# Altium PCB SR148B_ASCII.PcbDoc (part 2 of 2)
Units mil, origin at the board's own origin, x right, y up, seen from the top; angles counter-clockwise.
Board outline 3900 x 2475 mil, 6 copper layers (Top Layer, Signal Layer 1, Signal Layer 2, Signal Layer 3, Signal Layer 4, Bottom Layer), stack 60.536 mil thick; 89 components, 26 nets, 178 pads, 295 vias.
Unrouted connection lines stored in the file: 1.
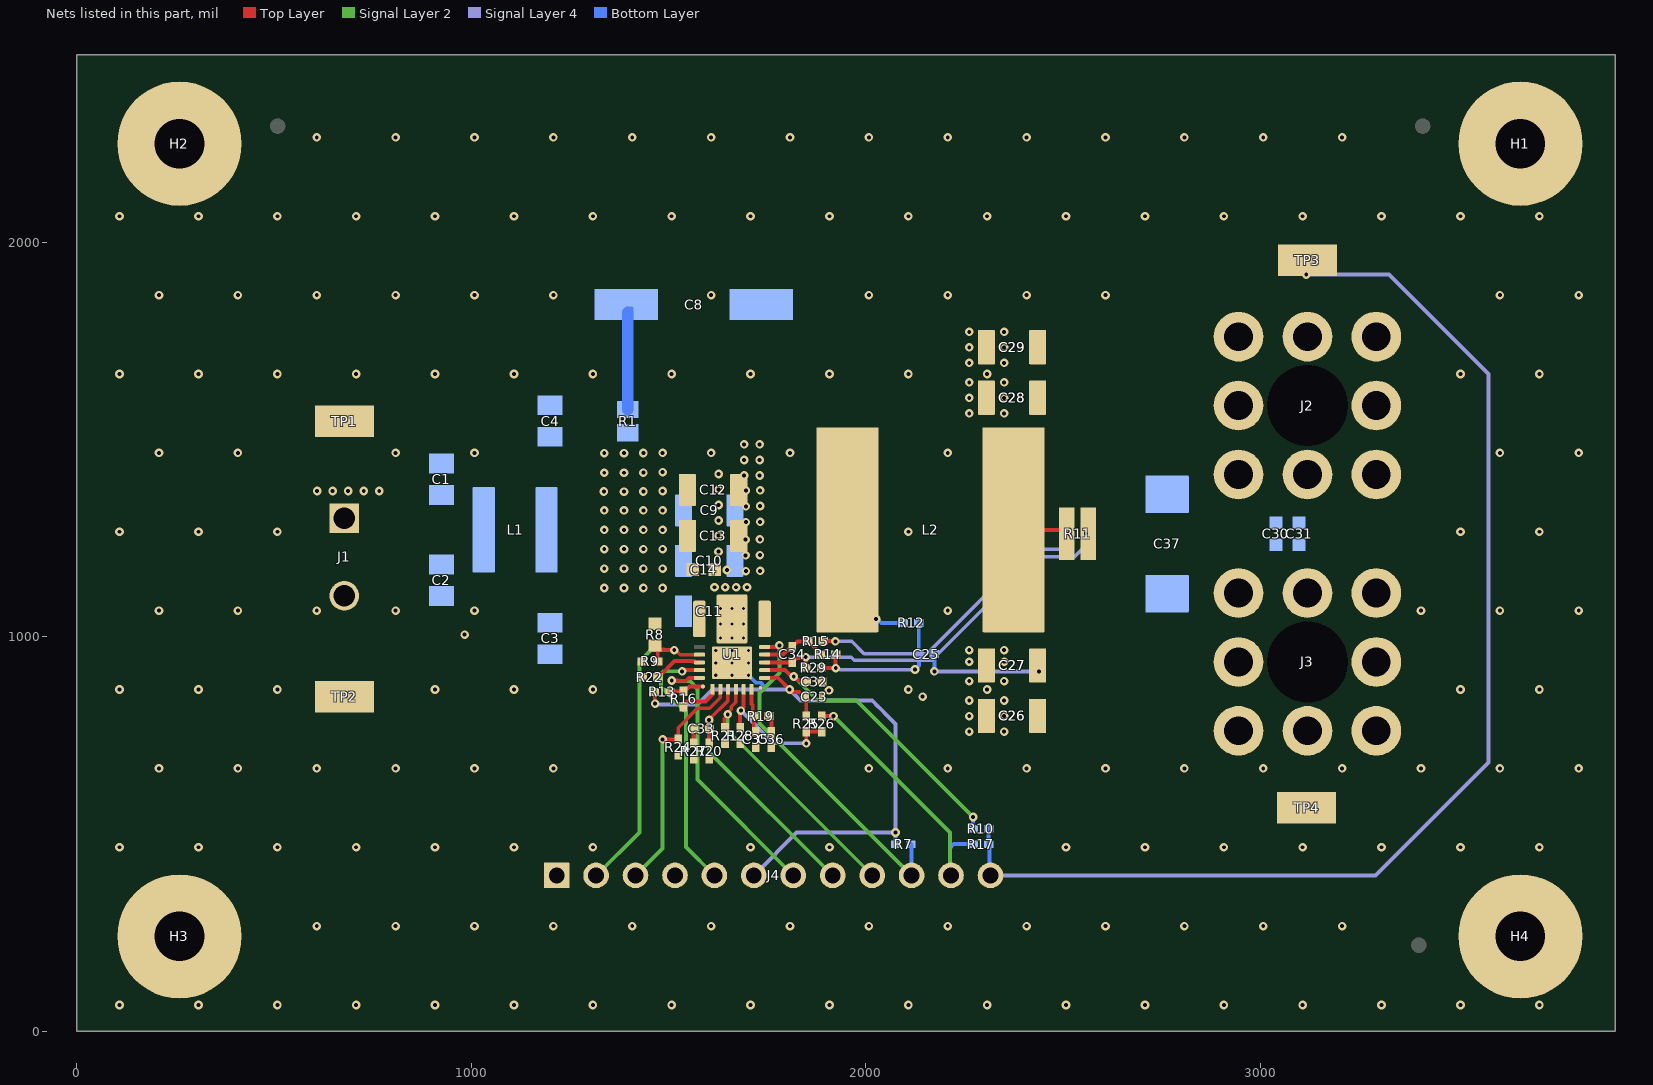
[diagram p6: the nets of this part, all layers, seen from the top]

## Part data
C1 C2 C3 C4: library part CMP-0008374-2, "CAP, CERM, 0.47 uF, 100 V, +/- 10%, X7R, 0805"
C8: library part CMP-0011203-2, "CAP, AL, 33 uF, 100 V, +/- 20%, 0.7 ohm, AEC-Q200 Grade 2, SMD"
C9 C10 C11 C12 C13: library part CMP-0087970-1, "10µF ±10% 100V Ceramic Capacitor X7S 1210 (3225 Metric)"
C14: library part CMP-0080063-1, "CAP, CERM, 0.01 µF, 100 V,+/- 10%, X8R, AEC-Q200 Grade 0, 0603"
C23: library part CMP-0086250-1, "CAP, CERM, 2.2 µF, 10 V,+/- 10%, X7S, AEC-Q200 Grade 1, 0402"
C25 C32: library part CMP-0080610-1, "CAP, CERM, 0.1 µF, 25 V,+/- 10%, X7R, AEC-Q200 Grade 1, 0402"
C26 C27 C28 C29: library part CMP-0096011-1, "Ceramic Capacitor for Automotive 47uF ±10% 10VDC X7S 1210 Embossed T/R"
C26 C27 C28 C29: library part CMP-0036912-1, "Cap Ceramic 22uF 25V X7R 20% Pad SMD 1210 +125°C Automotive T/R"
C30 C31: library part CMP-0006861-4, "CAP, CERM, 0.1 uF, 50 V, +/- 10%, X7R, 0603"
C33: library part CMP-0078224-1, "CAP, CERM, 0.01 µF, 50 V,+/- 10%, X8R, AEC-Q200 Grade 0, 0402"
C34: library part CMP-0006308-2, "CAP, CERM, 100 pF, 50 V, +/- 5%, C0G/NP0, AEC-Q200 Grade 1, 0402"
C35: library part CMP-0860832-1, "CAP, CERM, 47 pF, 50 V,+/- 5%, C0G/NP0, AEC-Q200 Grade 1, 0402"
C36: library part CMP-0006686-2, "CAP, CERM, 2700 pF, 50 V, +/- 10%, X7R, 0402"
C37: library part CMP-0124193-1, "100 µF 16 V Aluminum - Polymer Capacitors 2917 (7343 Metric) 12mOhm 2000 Hrs @ 105°C"
"CAUTION HOT SURFACE": library part CMP-0074837-2, "IEC 61010-1 Hot Surface Warning"
FID1 FID2 FID3 FID4 FID5 FID6: library part CMP-0077181-1, "Fiducial mark.  There is nothing to buy or mount."
H1 H2 H3 H4: library part CMP-0003617-1, "Machine Screw, Round, #4-40 x 1/4, Nylon, Philips panhead"
H5 H6 H7 H8: library part CMP-0003610-1, "Standoff, Hex, 0.5\"L #4-40 Nylon"
J1: library part CMP-0054978-1, "Therminal Block, 5 mm, 2-pole, Tin, TH"
J2 J3: library part CMP-0087729-1, "WP-THRSH 8 Pin PCB Screw Terminal, 85A, Solder, M5, Vertical"
J4: library part CMP-0075424-1, "Header, 100mil, 12x1, Gold, TH"
L1: library part CMP-0093175-1, "Shielded Power Inductors 3.3uH 20% tol, 6.5mOhm 16.6A"
L2: library part CMP-0123970-1, "Power Choke Coil 4.7uH 20% 100kHz 4.7mOhm 27A AECQ200 13.3x12.8x8.0mm SMT"
Logo1: library part CMP-0074844-1
Logo2: library part CMP-0074838-1, "Texas Instrument Corporate Signature"
Logo3: library part CMP-0074847-1, "FCC_disclaimer"
Logo4: library part CMP-0074769-1
R1: library part CMP-0020616-3, "RES, 0, 5%, 0.125 W, AEC-Q200 Grade 0, 0805"
R7 R29: library part CMP-0080661-1, "RES, 100 k, 1%, 0.0625 W, AEC-Q200 Grade 0, 0402"
R8: library part CMP-0022901-4, "RES, 200 k, 1%, 0.1 W, 0603"
R9 R12: library part CMP-0078779-1, "RES, 10.0 k, 1%, 0.2 W, AEC-Q200 Grade 0, 0402"
R10: library part CMP-0026129-2, "RES, 1.00, 1%, 0.063 W, AEC-Q200 Grade 0, 0402"
R11: library part CMP-0124890-1, "1 mOhms ±5% 1.5W Chip Resistor Wide 1206 (3216 Metric), 0612 Automotive AEC-Q200, Current Sense Metal Foil"
R13 R16 R26: library part CMP-0026449-2, "RES, 54.9 k, 1%, 0.063 W, AEC-Q200 Grade 0, 0402"
R14 R25 R27: library part CMP-0027007-2, "RES, 0, 5%, 0.063 W, AEC-Q200 Grade 0, 0402"
R15 R17: library part CMP-0026703-1, "RES, 49.9, 1%, 0.1 W, AEC-Q200 Grade 0, 0402"
R19: library part CMP-0025975-3, "RES, 11.0 k, 1%, 0.063 W, AEC-Q200 Grade 0, 0402"
R20: library part CMP-0026591-2, "RES, 8.66 k, 1%, 0.063 W, AEC-Q200 Grade 0, 0402"
R21 R24: library part CMP-0026605-2, "RES, 90.9 k, 1%, 0.063 W, AEC-Q200 Grade 0, 0402"
R22: library part CMP-0026187-2, "RES, 23.7 k, 1%, 0.063 W, AEC-Q200 Grade 0, 0402"
R28: library part CMP-0026783-1, "RES, 4.99 k, 0.1%, 0.063 W, 0402"
SH-J1 SH-J2: library part CMP-0078738-1, "Single Operation 2.54mm Pitch Open Top Jumper Socket"
TP1 TP2 TP3 TP4: library part CMP-0055162-1, "Test Point, Miniature, SMT"
U1: library part CMP-0125338-2, "LMG708B0"
ZZ1: library part CMP-0003616-3
ZZ2: library part CMP-0077236-1
ZZ3: library part CMP-0077237-1
ZZ4: library part CMP-0077238-1
ZZ5 ZZ6: library part CMP-0077238-1, "These assemblies must comply with workmanship standards IPC-A-610 Class 2, unless otherwise specified."

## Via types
v1: diameter 22, hole 10, Top Layer to Bottom Layer, tented both sides, 277 vias
v2: diameter 19.68, hole 7.87, Top Layer to Bottom Layer, tented both sides, 18 vias

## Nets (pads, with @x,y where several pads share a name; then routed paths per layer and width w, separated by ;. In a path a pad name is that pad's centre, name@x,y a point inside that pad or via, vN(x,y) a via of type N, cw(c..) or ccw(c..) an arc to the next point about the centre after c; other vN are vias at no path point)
AGND: C35.2 C36.2 R9.1 R16.1 R20.1 R21.1 R22.1 R24.1 R27.1 R28.1 U1.1 U1.16 | length 90.6
  Top Layer w10: 1541.77,835.62 1593.73,835.62 1611.79,853.68 U1.16@1611.79,866.8
BIAS: C32.1 R10.1 U1.3 | length 738.5
  Top Layer w9.8: U1.3@1743.22,915.43 1794.92,915.43 1811.51,898.84 v1(1817.45,898.84)
  Top Layer w10: v1(1817.45,898.84) 1819.32,898.84 1829.3,888.85 1843.03,888.85 C32.1@1846.88,885
  Signal Layer 2 w10: v1(1817.45,898.84) 1878.36,837.93 1977.15,837.93 v1(2272.43,542.65)
  Bottom Layer w10: 2272.43,522.97 v1(2272.43,542.65)
COMP: C35.1 R19.2 U1.21 | length 109.3
  Top Layer w9: R19.2@1709.02,800.6 1708.31,801.31 1708.96,801.31 1714,806.35 1714,827.32 ; R19.2@1714.61,798.59 1716.49,796.71 C35.1@1716.49,759
  Top Layer w10: U1.21@1710.21,866.8 1710.21,829.28 1711.4,828.09
EN: J4.2 R8.1 R9.2 U1.11 | length 851.2
  Top Layer w9: v1(1514.55,965.88) 1518.07,965.88 1529.56,954.39 U1.11@1578.32,954.39
  Top Layer w10: R8.1@1465.34,975.72 1472.69,968.38 R9.2@1472.69,937.2 ; R8.1@1465.34,977.69 1476.09,966.94 1487.49,966.94 1488.55,965.88 v1(1514.55,965.88)
  Signal Layer 2 w10: J4.2@1317.7,395.02 1425.97,503.28 1425.97,936.35 1455.5,965.88 v1(1514.55,965.88)
FB: R25.1 R26.1 R28.2 U1.20 | length 368.8
  Top Layer w10: R28.2@1676.94,771.66 1681.67,776.4 1681.67,810.55 v1(1683.46,812.34) ; v1@1681.87,814 1689.85,821.98 U1.20@1689.85,867.24 ; v1(1849.2,729.66) R25.1@1849.2,759.19 R26.1@1888.57,759.19
  Signal Layer 4 w9.8: v1(1683.46,812.34) 1766.14,729.66 v1(1849.2,729.66)
FPWM/SYNC: J4.5 U1.13 | length 668.6
  Top Layer w9.8: v1(1534.67,912.11) 1538.01,915.45 U1.13@1577.84,915.45
  Signal Layer 2 w9.8: v1(1534.67,912.11) 1534.35,912.42 1486.52,912.42 1480.78,906.68 1480.78,872.22 1544.08,808.92 1544.08,466.92 J4.5@1615.98,395.02
GND: C1.2 C2.2 C3.2 C4.2 C8.2 C9.2 C10.2 C11.2 C12.2 C13.2 C14.2 C23.2 C26.1 C27.1 C28.1 C29.1 C30.2 C31.2 C32.2 C37.1 H1.1 H2.1 H3.1 H4.1 J1.2 J3.1 J4.1 J4.4 TP2.1 TP4.1 U1.8 U1.22 | length 54.6
  Bottom Layer w9.8: v2@1701.88,902.94 1721.77,883.04 1734.22,883.04 1734.22,882.84 1744.02,873.05
  other v1: 108,66 308,66 508,66 708,66 908,66 1108,66 1308,66 1508,66 1708,66 1908,66 2108,66 2308,66 2508,66 2708,66 2908,66 3108,66 3308,66 3508,66 3708,66 608,266 808,266 1008,266 1208,266 1408,266 1608,266 1808,266 2008,266 2208,266 2408,266 2608,266 2808,266 3008,266 3208,266 108,466 308,466 508,466 708,466 908,466 1108,466 1308,466 1708,466 1908,466 2508,466 2708,466 2908,466 3108,466 3308,466 3508,466 3708,466 208,666 408,666 608,666 808,666 1008,666 1208,666 2008,666 2208,666 2408,666 2608,666 2808,666 3008,666 3208,666 3408,666 3608,666 3808,666 2262.58,759.19 2351.17,759.19 2262.58,798.56 2351.17,798.56 2262.58,837.93 2351.17,837.93 2144.47,847.77 1907,864 108,866 308,866 508,866 908,866 1108,866 1308,866 2108,866 2308,866 3508,866 3708,866 2262.58,887.14 2351.17,887.14 2262.58,936.35 2351.17,936.35 2262.58,965.88 2351.17,965.88 983.06,1005.25 208,1066 408,1066 608,1066 808,1066 1008,1066 2208,1066 3408,1066 3608,1066 3808,1066 1616.4,1125.26 1643.87,1125.26 1671.34,1125.26 1698.81,1125.26 1696.08,1166.08 1732.24,1166.79 1648,1169 1695.42,1206.08 1731.58,1206.79 1626.64,1215.44 1695.42,1246.08 1731.58,1246.79 1626.64,1256.07 108,1266 308,1266 508,1266 2108,1266 3508,1266 3708,1266 1696.08,1290.44 1732.24,1291.15 1627,1294.43 1696.08,1330.44 1732.24,1331.15 1627,1333.8 1696.08,1370.44 1732.24,1371.15 1627,1373.17 1691.72,1408.8 1731.09,1408.8 1627,1412.54 1691.72,1448.17 1731.09,1448.17 208,1466 408,1466 808,1466 1008,1466 1608,1466 1808,1466 2208,1466 3608,1466 3808,1466 1691.72,1487.54 1731.09,1487.54 2262.58,1566.28 2351.17,1566.28 2262.58,1605.65 2351.17,1605.65 2262.58,1645.02 2351.17,1645.02 108,1666 308,1666 508,1666 708,1666 908,1666 1108,1666 1308,1666 1508,1666 1708,1666 1908,1666 2108,1666 2308,1666 3508,1666 3708,1666 2262.58,1694.23 2351.17,1694.23 2262.58,1733.6 2351.17,1733.6 2262.58,1772.97 2351.17,1772.97 208,1866 408,1866 608,1866 808,1866 1008,1866 1208,1866 1608,1866 2008,1866 2208,1866 2408,1866 2608,1866 3608,1866 3808,1866 108,2066 308,2066 508,2066 708,2066 908,2066 1108,2066 1308,2066 1508,2066 1708,2066 1908,2066 2108,2066 2308,2066 2508,2066 2708,2066 2908,2066 3108,2066 3308,2066 3508,2066 3708,2066 608,2266 808,2266 1008,2266 1208,2266 1408,2266 1608,2266 1808,2266 2008,2266 2208,2266 2408,2266 2608,2266 2808,2266 3008,2266 3208,2266
  other v2: 1619.66,902.23 1661,902.23 1702.34,902.23 1619.66,933.72 1661,933.72 1702.34,933.72 1619.66,965.22 1661,965.22 1702.34,965.22 1631.47,996.32 1661,996.32 1690.53,996.32 1631.47,1031.76 1661,1031.76 1690.53,1031.76 1631.47,1071.13 1661,1071.13 1690.53,1071.13
IMON: C33.2 J4.8 R20.2 U1.18 | length 682.7
  Top Layer w9: v1(1603.13,788.72) 1603.13,790.35 1650.67,837.89 U1.18@1650.67,867.22
  Top Layer w10: R20.2@1603.13,729.66 1603.13,759.19 v1(1603.13,788.72)
  Signal Layer 2 w10: v1(1603.13,788.72) 1603.13,707.86 1915.98,395.02 J4.8@1918.09,395.02
ISET: J4.9 R21.2 U1.19 | length 664.2
  Top Layer w9: v1@1650.6,802.6 1650.6,807.41 1659.09,815.89 1659.09,822.43 1670.49,833.84 U1.19@1670.49,867.09
  Top Layer w10: R21.2@1637.74,771.49 1641.3,775.04 1641.3,790.79 v1@1649.07,798.56
  Signal Layer 2 w9: v1(1650.23,802.97) 1650.23,761.3 J4.9@2016.52,395.02
NetC1_1: C1.1 C2.1 J1.1 L1.1 TP1.1
  other v1: 609.04,1369.43 648.41,1369.43 687.78,1369.43 727.15,1369.43 766.52,1369.43
NetC8_1: C8.1 R1.1 | length 260
  Bottom Layer w10: C8.1@1396.44,1822.18 C8.1@1406.28,1832.02
  Bottom Layer w30: R1.1@1396.44,1576.12 C8.1@1396.44,1822.18
NetC25_1: C25.1 R12.2 R14.2 R29.2 | length 399.2
  Top Layer w10: R29.2@1887.69,921 1888.19,920.5 1924.5,920.5 v1@1925,921 ; R14.2@1923.69,955 1923.84,954.84 1923.84,921.16 v1@1925,920
  Signal Layer 4 w9: v1(1924,920) 1926.49,917.51 1934.05,917.51 1934.89,916.67 v1(2124.79,916.67)
  Bottom Layer w10: v1(2124.79,916.67) 2124.79,917.51 2134.63,927.36 2134.63,955.72 C25.1@2134.32,956.04 2134.47,956.2 2134.47,1035.53 R12.2@2134,1036
NetC33_1: C33.1 R27.2 | length 29.5
  Top Layer w10: R27.2@1563.76,729.66 C33.1@1563.76,759.19
NetC34_1: C34.1 R14.1 R15.1 U1.5 | length 174
  Top Layer w10: U1.5@1743.68,954.39 1790.39,954.39 1803.87,967.87 1809.16,967.87 1814,972.72 C34.1@1814,974.68 ; C34.1@1814,976.65 1818.84,981.5 1820.81,981.5 1826.5,987.19 1854.19,987.19 R15.1@1855,988 ; R14.1@1882,956 1881.35,956 1877.5,959.84 1877.5,964.81 1860.13,982.19 1860.13,984.16 R15.1@1855.28,989 ; R15.1@1855.28,989 R15.1@1853.32,989 R15.1@1855.28,989
NetC36_1: C36.1 R19.1 | length 41.2
  Top Layer w10: R19.1@1753.98,798.59 1755.77,798.59 1760.61,793.75 C36.1@1760.61,761.16
NetL2_1: L2.1 R12.1 U1.7 | length 73
  Bottom Layer w10: v1(2026.36,1044.62) 2029.61,1044.62 2039.45,1034.78 R12.1@2095.26,1034.78
NetL2_2: L2.2 R11.1 R15.2 | length 925.8
  Top Layer w10: R15.2@1892.69,989 1893.19,988.5 1921.5,988.5 v1@1923,987 ; L2.2@2380.69,1271 2510.61,1271 2518.49,1263.13 R11.1@2518.49,1261.16
  Signal Layer 4 w9: v1(1923,988) 1964.69,988 1995.77,956.92 2155.19,956.92 2420.06,1221.79 2508.65,1221.79 2518.49,1231.63 v1@2518.49,1261.16
  other v1: 2516,1261.16
NetR22_2: R22.2 U1.12 | length 120.9
  Top Layer w10: R22.2@1475.18,898.16 1514.92,937.89 1560.3,937.89 1560.73,937.47 1566.86,937.47 1569.62,934.71 U1.12@1578.32,934.71
PG: J4.10 R7.1 U1.6 | length 881.4
  Top Layer w9.8: U1.6@1743.22,974.08 1773.78,974.08 1777.7,978 v1(1781,978)
  Signal Layer 2 w10: v1(1781,978) 1781,907.53 1731.09,857.61 1731.09,779.91 2114.94,396.05 J4.10@2114.94,395.02
  Bottom Layer w10: J4.10@2114.94,395.02 2115.62,395.69 2115.62,473.08 R7.1@2114.94,473.76
RT: R13.1 R16.2 U1.15 | length 81.6
  Top Layer w10: R13.1@1505,863 1506.42,861.58 R16.2@1534.07,861.58 ; R16.2@1539,864.48 1543.11,868.59 1548.68,868.59 1553.68,873.6 1587.09,873.6 U1.15@1587.18,873.68
SYNCOUT: J4.7 U1.14 | length 725.6
  Top Layer w9.8: v1@1508.12,888.65 1508.3,888.47 1524.68,888.47 1524.82,888.33 1544.51,888.33 1551.52,895.34 U1.14@1578.32,895.34
  Signal Layer 2 w10: v1@1508.12,888.65 1509.63,887.14 1553.92,887.14 1573.61,867.46 1573.61,637.39 J4.7@1819.67,391.33
  other v1: 1508.12,889
VBODE: J4.11 R17.1 R26.2 | length 687.4
  Top Layer w10: R26.2@1888.57,798.56 v1(1918.09,798.56)
  Signal Layer 2 w10: v1(1918.09,798.56) 2213.37,503.28 J4.11@2213.37,395.02
  Bottom Layer w10: J4.11@2213.37,395.02 2213.37,463.91 2223.21,473.76 R17.1@2272.43,473.76
VCC: C23.1 J4.6 R7.2 R13.2 R25.2 U1.2 | length 1560.4
  Top Layer w9.8: U1.2@1743.19,895.77 1777.24,895.77 v1(1807.03,865.97)
  Top Layer w10: R13.2@1464.13,861.39 1465.07,860.45 1465.07,829.93 v1@1467,828 ; v1@1809.83,867.46 1809.83,866.43 1816.75,859.5 1830.57,859.5 1841.32,848.76 1841.32,847.77 ; R25.2@1849.2,808.4 C23.1@1849.2,847.77
  Signal Layer 4 w9.8: v1(1466,830) 1467.91,828.09 1573.61,828.09 1611.49,865.97 v1(1807.03,865.97)
  Signal Layer 4 w10: J4.6@1721.24,395.02 1721.24,399.64 1824.89,503.28 v1(2075.57,503.28) 2075.57,778.87 2060.81,793.64 2060.81,794.19 2031.83,823.17 2031.28,823.17 2016.52,837.93 1835.08,837.93 v1(1807.03,865.97)
  Bottom Layer w10: R7.2@2075.57,473.76 v1(2075.57,503.28)
VIN: C3.1 C4.1 C9.1 C10.1 C11.1 C12.1 C13.1 C14.1 L1.2 R1.2 R8.2 U1.9
  other v1: 1337,1123.36 1387,1123.36 1436,1123.36 1485,1123.36 1337,1172.57 1387,1172.57 1436,1172.57 1485,1172.57 1337,1221.79 1387,1221.79 1436,1221.79 1485,1221.79 1337,1271 1387,1271 1436,1271 1485,1271 1337,1320.21 1387,1320.21 1436,1320.21 1485,1320.21 1336,1368 1387,1367.65 1436,1367.92 1485,1369.43 1337,1415.58 1387,1415.58 1436,1415.85 1485,1417 1337,1465.49 1387,1465.49 1436,1465.76 1485,1466
VOUT: C25.2 C26.2 C27.2 C28.2 C29.2 C30.1 C31.1 C34.2 C37.2 J2.1 J4.12 R10.2 R11.2 R17.2 R29.1 TP3.1 U1.4 | length 4377.5
  Top Layer w10: U1.4@1743.68,934.71 1743.76,934.79 1811.79,934.79 C34.2@1813,936 ; C34.2@1814,935.31 1814,937.28 1818.84,942.13 1820.81,942.13 1824.39,945.7 1844.7,945.7 v1@1848,949 ; v1(1848,948) 1848.16,947.84 1848.16,921.16 R29.1@1848.32,921
  Signal Layer 4 w9: v1(1848,948) 1963.04,948 1971,940.04 2167.85,940.04 2429.91,1202.1 2528.33,1202.1 2557.86,1231.63 v1(2557.86,1261.16) ; J2.1@3294.61,1760.61 J2.1@3306,1772
  Signal Layer 4 w10: v1(2174,912) v1(2439.75,912) ; J4.12@2316.3,394.69 3292.69,394.69 3579,681 3579,1666 3327,1918 3118,1918 v1@3116,1920
  Bottom Layer w10: v1@2174,916.67 C25.2@2174,956.04 ; R17.2@2311.8,473.76 2314.05,471.5 2314.05,397.95 J4.12@2317,395 ; R10.2@2311.8,513.13 2311.8,475.2 R17.2@2313,474
  other v1: 3117,1918
VSET: J4.3 R24.2 U1.17 | length 595.4
  Top Layer w9: R24.2@1524.39,739.5 1524.39,769.03 1573.61,818.24 1604.41,818.24 1630.99,844.83 U1.17@1630.99,867.22
  Top Layer w10: v1(1485.02,739.5) R24.2@1524.39,739.5
  Signal Layer 2 w10: J4.3@1435.81,395.02 1434.25,396.57 1434.25,412.65 1485.02,463.42 v1(1485.02,739.5)
pads on no net: FID1.1 FID2.1 FID3.1 FID4.1 FID5.1 FID6.1 H5.0 H6.0 H7.0 H8.0 J2. J3. U1.10

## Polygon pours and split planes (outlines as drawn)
NetL2_2 on Top Layer "TOP_LAYER_NETL2_2_P825" (solid, remove dead copper, pour order 825): 2310.06,1009.94 2295.06,1009.94 2295.06,1531.98 2479.02,1531.98 cw(c2479.02,1479.94) 2531.06,1479.94 2531.06,1065.14 cw(c2476.02,1064.98) 2476.02,1009.94
VOUT on Top Layer "TOP_LAYER_VOUT_P814" (solid, remove dead copper, pour order 814): 2405,1846 2405,1550 2405,1416 2405,988 2404,987 2404,736 2827,736 2828,737 2825,740 2825,1216 3395,1216 3395,1846 3220,1846 3220,2018 3020,2018 3020,1846
GND on Top Layer "TOP_LAYER_GND_P824" (solid, remove dead copper, pour order 824): 0,3 4,-1 3898,-1 3898,2475 3896,2477 0,2477
AGND on Top Layer "TOP_LAYER_AGND_P794" (solid, remove dead copper, pour order 794): 1728,881 1793.48,881 1826.14,848.35 1826.14,660.19 1818.55,652.6 1430.44,652.6 1407.21,675.82 1407.21,995.41 1501.33,995.41 1501.33,748.98 1772.6,748.98 1772.6,819.63 1774.37,821.4 1728,821.4
VIN on Top Layer "TOP_LAYER_VIN_P775" (solid, remove dead copper, pour order 775): 1046,1497.38 1583.45,1497.38 1583.45,1133.2 1594.46,1122.2 1594.46,999.29 1046,999.29
NetC1_1 on Top Layer "TOP_LAYER_NETC1_1_P796" (solid, remove dead copper, pour order 796): 573,1623 573,1236.55 777,1236.55 777,1623
AGND on Top Layer "TOP_LAYER_AGND_P800" (solid, remove dead copper, pour order 800): 1549,842 1549,813.32 1504.71,769.03 1504.71,739.5 1489,739.5 1489,842
NetL2_1 on Top Layer "TOP_LAYER_NETL2_1_P805" (solid, remove dead copper, pour order 805): 1859.04,1537.51 1859.04,1211.4 1721.27,1130.26 1721.27,997.85 1762,997.85 1777,1009.17 2036.2,1009.17 2036.2,1537.51
VOUT on Bottom Layer "BOTTOM_LAYER_VOUT_P792" (solid, remove dead copper, pour order 792): 2673,1931 2673,1274 3442,1274 3453,1285 3451,1287 3451,1931
NetC1_1 on Bottom Layer "BOTTOM_LAYER_NETC1_1_P797" (solid, remove dead copper, pour order 797): 589.35,1389.11 1061.8,1389.11 1061.8,1152.89 589.35,1152.89
VIN on Bottom Layer "BOTTOM_LAYER_VIN_P815" (solid, remove dead copper, pour order 815): 1258.65,1005.25 1583.45,1005.25 1583.45,1536.75 1160.22,1536.75 1160.22,1005.25
GND on Bottom Layer "BOTTOM_LAYER_GND_P816" (solid, remove dead copper, pour order 816): -1,2473 -1,5 3,1 3900,1 3900,2472
NetC1_1 on Signal Layer 4 "SIGNAL_LAYER_4_NETC1_1_P783" (solid, remove dead copper, pour order 783): 589.35,1398.95 589.35,1392.7 589.35,1241.47 786.2,1241.47 786.2,1398.95
GND on Signal Layer 4 "SIGNAL_LAYER_4_GND_P818" (solid, remove dead copper, pour order 818): -6,2477 -6,3 3900,3 3900,2477
NetC1_1 on Signal Layer 3 "SIGNAL_LAYER_3_NETC1_1_P782" (solid, remove dead copper, pour order 782): 591.15,1397.25 589.35,1395.45 589.35,1241.47 786.2,1241.47 786.2,1398.95 589.35,1398.95
GND on Signal Layer 3 "SIGNAL_LAYER_3_GND_P819" (solid, remove dead copper, pour order 819): -2,2473 1,2470 1,0 3890,0 3893,3 3893,2477
NetC1_1 on Signal Layer 2 "SIGNAL_LAYER_2_NETC1_1_P781" (solid, remove dead copper, pour order 781): 589.35,1398.95 589.35,1241.47 786.2,1241.47 786.2,1398.95
GND on Signal Layer 2 "SIGNAL_LAYER_2_GND_P820" (solid, remove dead copper, pour order 820): -2,2480 -2,0 3900,0 3900,2477
NetC1_1 on Signal Layer 1 "SIGNAL_LAYER_1_NETC1_1_P776" (solid, remove dead copper, pour order 776): 589.35,1398.95 589.35,1251.32 796.05,1251.32 796.05,1398.95
GND on Signal Layer 1 "SIGNAL_LAYER_1_GND_P821" (solid, remove dead copper, pour order 821): 1,2473 -6,2466 -6,3 3897,3 3900,0 3900,2473

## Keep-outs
Keep-Out Layer:
  lines w10: 3900,0 0,0 0,2471.61 3900,2471.61 3900,2475
  text ".Layer_Name" at 577,-858.49 h60

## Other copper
Top Layer:
  text ".Layer_Name" at 577,-858.49 h60
Signal Layer 1:
  text ".Layer_Name" at 570.87,-856.3 h60
Signal Layer 2:
  text ".Layer_Name" at 570.87,-856.3 h60
Signal Layer 3:
  text ".Layer_Name" at 580.71,-856.3 h60
Signal Layer 4:
  text ".Layer_Name" at 580.71,-856.3 h60
Bottom Layer:
  text ".Layer_Name" at 577,-858.49 h60

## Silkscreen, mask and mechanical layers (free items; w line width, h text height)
Top Overlay:
  text ".PRJ_Title" at 2116.3,2332.83 h60
  text "'.PRJ_Number'.PCB_Rev" at 2116.3,2224.57 h60
  text "VOUT+" at 3411,1576 h50
  text "VIN+" at 272.87,1407.64 h50
  text "VIN-" at 272.87,907.83 h50
  text "VOUT-" at 3410,907 h50
  text "EN" at 1327.54,257.22 h30 r90
  text "PG" at 2134.63,247.38 h30 r90
  text "GND" at 1214.91,239.53 h30 r90
  text "GND" at 1534.24,237.54 h30 r90
  text "VCC" at 1731.09,237.54 h30 r90
  text "VSET" at 1435.81,217.85 h30 r90
  text "IMON" at 1937.78,217.85 h30 r90
  text "ISET" at 2036.2,217.85 h30 r90
  text "VOUT" at 2331.48,217.85 h30 r90
  text "BODE" at 2233.06,208.01 h30 r90
  text "SYNCOUT" at 1833,122 h30 r90
  text "FPWM/SYNC" at 1631,57 h30 r90
  text ".Layer_Name" at 577,-858.49 h60
Bottom Overlay:
  text ".Layer_Name" at 577,-858.49 h60
Top Paste:
  text ".Layer_Name" at 577,-858.49 h60
Bottom Paste:
  text ".Layer_Name" at 577,-858.49 h60
Top Solder:
  text ".Layer_Name" at 577,-858.49 h60
  text ".Layer_Name" at 577,-858.49 h60
Bottom Solder:
  text ".Layer_Name" at 577,-858.49 h60
Drill Guide:
  text ".Layer_Name" at 577,-858.49 h60
M1 Board Outline:
  the board outline again, w10
  text ".Layer_Name" at 577,-858.49 h60
M2 Board Dimensions:
  rectangle: 0,-275 125,-150
  rectangle: 125,-400 500,-275
  lines w7: 0,-275 1000,-275 ; 125,-400 125,-150 ; 250,-400 250,-150 ; 500,-400 500,-150 ; 750,-400 750,-150 ; 0,-400 1000,-400 1000,-150 0,-150 0,-400
  text ".Layer_Name" at 577,-858.49 h60
M3 3D STEP Top:
  text ".Layer_Name" at 577,-858.49 h60
M4 3D STEP Bottom:
  text ".Layer_Name" at 577,-858.49 h60
M5 Assembly Top:
  lines w10: -292,-930.17 6308,-930.17 ; -292,-726.83 6310,-726.83 ; -292,-523.5 -292,-1133.5 3713,-1133.5 6310,-1133.5 6310,-523.5 -291.5,-523.5 -291.5,-1133.5 1284,-1133.5 ; 2173,-1133.5 2173,-523.5 ; 3440,-726.83 3440,-523.5 ; 4280,-726.83 4280,-523.5 ; 4902,-1140 4902,-937.17
  text "COMPONENTS MARKED 'DNP' SHOULD NOT BE POPULATED." at 1153.5,-318.5 h60
  text "ASSEMBLY VARIANT:" at 1153,-434 h60
  text ".VariantName" at 2189,-434 h60
  text "PCB VIEWED FROM TOP SIDE" at -228.5,-655.67 h60
  text "BOARD #:" at 2248,-655.67 h60
  text ".PRJ_Number" at 2793.5,-655.67 h60
  text "REV:" at 3638,-655.67 h60
  text ".PCB_Rev" at 3929.5,-655.67 h60
  text "SVN REV:" at 4476,-655.67 h60
  text ".VersionControl_RevNumber" at 4982,-655.67 h60
  text "TID #:" at 2248,-859 h60
  text ".TID" at 2793.5,-859 h60
  text "PLOT NAME =" at -228.5,-1064.34 h60
  text ".plot_File_Name" at 577,-1064.34 h60
  text "GENERATED    :" at 2250,-1064.34 h60
  text ".Print_Date" at 3119.5,-1064.34 h60
  text ".Print_Time" at 3848.5,-1064.34 h60
  text "TEXAS INSTRUMENTS" at 5113,-1064.34 h60
M6 Assembly Bottom:
  lines w10: -292.5,-727.33 6309.5,-727.33 ; -290.5,-930.67 6309.5,-930.67 ; 1115.5,-1140.5 1115.5,-937.67 ; 1737.5,-727.33 1737.5,-524 ; 2577.5,-727.33 2577.5,-524 ; 3844.5,-1134 3844.5,-524 ; 4733.5,-1134 6309,-1134 6309,-524 -292.5,-524 -292.5,-1134 2304.5,-1134 6309.5,-1134 6309.5,-524
  text "COMPONENTS MARKED 'DNP' SHOULD NOT BE POPULATED." at 6102,-318 h60
  text ".VariantName" at 5058,-434 h60
  text "ASSEMBLY VARIANT:" at 6097,-434 h60
  text ".VersionControl_RevNumber" at 1035.5,-656.17 h60
  text "SVN REV:" at 1541.5,-656.17 h60
  text ".PCB_Rev" at 2088,-656.17 h60
  text "REV:" at 2379.5,-656.17 h60
  text ".PRJ_Number" at 3224,-656.17 h60
  text "BOARD #:" at 3769.5,-656.17 h60
  text "PCB VIEWED FROM BOTTOM SIDE" at 6246,-656.17 h60
  text ".TID" at 3224,-859.5 h60
  text "TID #:" at 3769.5,-859.5 h60
  text "TEXAS INSTRUMENTS" at 904.5,-1064.84 h60
  text ".Print_Time" at 2169,-1064.84 h60
  text ".Print_Date" at 2898,-1064.84 h60
  text "GENERATED    :" at 3767.5,-1064.84 h60
  text ".plot_File_Name" at 5440.5,-1064.84 h60
  text "PLOT NAME =" at 6246,-1064.84 h60
M9 Title Sheet:
  lines w10: -491.5,1041.5 -291.5,1041.5 ; -491.5,3416.5 -291.5,3416.5 ; -491.5,5791.5 -291.5,5791.5 ; 2008.5,-1333.5 2008.5,-1133.5 ; 2008.5,7966.5 2008.5,8166.5 ; 4508.5,-1333.5 4508.5,-1133.5 ; 4508.5,7966.5 4508.5,8166.5 ; 6321,-1133.5 6321,-523.5 11303.5,-523.5 ; 7008.5,-1333.5 7008.5,-1133.5 ; 7008.5,7966.5 7008.5,8166.5 ; 9508.5,-1333.5 9508.5,-1133.5 ; 9508.5,7966.5 9508.5,8166.5 ; 11303.5,-1133.5 11303.5,-523.5 ; 11303.5,-823.5 14303.5,-823.5 ; 11303.5,-223.5 14303.5,-223.5 ; 11304.5,370.5 14304.5,370.5 ; 12008.5,-1333.5 12008.5,-1133.5 ; 12008.5,7966.5 12008.5,8166.5 ; 12808.5,-1123.5 12808.5,-523.5 ; 14303.5,-523.5 11303.5,-523.5 ; 14303.5,76.5 11303.5,76.5 ; 14308.5,66.5 14308.5,-1133.5 ; 14308.5,871 11304.5,871 11303.5,871 11303.5,370.5 11303.5,76.5 ; 14308.5,1041.5 14508.5,1041.5 ; 14308.5,3416.5 14508.5,3416.5 ; 14308.5,5791.5 14508.5,5791.5 ; 11303.5,-523.5 11303.5,76.5 ; 14308.5,-1133.5 14308.5,7966.5 -291.5,7966.5 -291.5,-1133.5 14308.5,-1133.5 ; -491.5,-1333.5 -491.5,8166.5 14508.5,8166.5 14508.5,-1333.5 -491.5,-1333.5
  text "1" at 739.84,8036.5 h70
  text "2" at 3235.5,8036.5 h70
  text "3" at 5724.84,8036.5 h70
  text "4" at 8231.51,8036.5 h70
  text "5" at 10730.5,8036.5 h70
  text "6" at 13235.5,8036.5 h70
  text "A" at -416.5,6893.5 h70
  text "A" at 14383.5,6893.5 h70
  text "B" at -416.5,4513.5 h70
  text "B" at 14383.5,4513.5 h70
  text "C" at -416.5,2138.5 h70
  text "C" at 14383.5,2138.5 h70
  text "PROJECT TITLE:" at 11343.5,277.5 h45
  text ".PRJ_Title" at 11393.5,144.17 h70
  text "DESIGNED FOR:" at 11343.5,-23.5 h45
  text ".PRJ_Customer" at 11393.5,-163.5 h70
  text "D" at -416.5,-231.5 h70
  text "D" at 14383.5,-231.5 h70
  text "FILE NAME:" at 11343.5,-323.5 h45
  text ".PCB_File_Name_No_Path" at 11393.5,-443.5 h70
  text "Texas Instruments (TI) and/or its licensors do not warrant the accuracy or completeness of this specification" at 6374,-605.34 h45
  text "ENGINEER:" at 11343.5,-613.5 h45
  text "LAYOUT BY:" at 12848.5,-613.5 h45
  text "or any information contained therein. TI and/or its licensors do not warrant that this design will meet" at 6329.01,-718 h45
  text ".PRJ_Engineer" at 11393.5,-768.49 h70
  text ".PCB_Layout" at 12899,-768.49 h70
  text "the specifications, will be suitable for your application or fit for any particular purpose, or will operate in" at 6329.01,-830.67 h45
  text ".Layer_Name" at 577,-858.49 h60
  text "ALTIUM DESIGNER VERSION:" at 12848.5,-923.5 h45
  text "an implementation. TI and/or its licensors do not warrant that the design is production worthy. You should" at 6329.01,-943.33 h45
  text "completely validate and test your design implementation to confirm the system functionality for your application." at 6374,-1056 h45
  text ".print_Scale" at 11393.5,-1056.83 h70
  text ".Application_BuildNumber" at 12899,-1056.83 h70
  text "1" at 739.84,-1263.5 h70
  text "2" at 3235.5,-1263.5 h70
  text "3" at 5724.84,-1263.5 h70
  text "4" at 8231.51,-1263.5 h70
  text "5" at 10730.5,-1263.5 h70
  text "6" at 13235.5,-1263.5 h70
M10 Fab Notes:
  drawing of 189 lines, arcs and shapes, not listed
  text "DESIGN INFORMATION" at 12382.02,6356.17 h60
  text "MIN. TRACK WIDTH:" at 11737.46,6224.05 h60
  text "8" at 12833.7,6224.05 h60
  text "MIL" at 12988.46,6224.05 h60
  text "7.874" at 12667.32,6102.36 h60
  text "MIN. CLEARANCE:" at 11737.46,6099.92 h60
  text "MIL" at 12988.46,6099.92 h60
  text "MIN. VIA PAD SIZE:" at 11737.46,5975.8 h60
  text "24" at 12803.71,5975.8 h60
  text "MIL" at 12988.46,5975.8 h60
  text "0.05mm (2MIL)" at 12432.46,5845.9 h60
  text "MINIMUM ANNULAR RING" at 11408.23,5837.67 h60
  text "EXTERNAL" at 13140.46,5837.67 h60
  text "PER" at 11608.23,5727.55 h60
  text "IPC-D-275 CLASS 2 LEVEL C" at 11828.23,5727.54 h60
  text "MIL, HOLES" at 13316.46,5627.07 h60
  text "+/-" at 12924,5618.48 h60
  text "+/-" at 13778,5618.48 h60
  text "REGISTRATION TOLERANCES:" at 11408.23,5617.42 h60
  text "METAL" at 12608,5617.42 h60
  text "5" at 13184.2,5617.42 h60
  text "3" at 14017.2,5617.42 h60
  text "MIL" at 14133.46,5617.42 h60
  text "HOLE SIZE TOLERANCE (UNLESS OTHERWISE SPECIFIED):" at 11408.23,5519.1 h60
  text "+/-" at 13778,5516.23 h60
  text "3" at 14017.2,5515.17 h60
  text "MIL" at 14133.46,5515.17 h60
  text "MATERIAL:" at 11333.46,5377.52 h60
  text "FR-4 High Tg" at 12319.9,5249 h60
  text "X" at 12175.46,5241.01 h60
  text "FR-4" at 11754.46,5236.49 h60
  text "OTHER" at 13242.46,5236.49 h60
  text "62 MIL (1.6mm) +/-10%" at 12074.56,5093.46 h60
  text "X" at 11954.46,5091.01 h60
  text "THICKNESS:" at 11408.23,5085.24 h60
  text "OTHER" at 13359.46,5085.24 h60
  text "TOLERANCE:" at 11408.23,4946.92 h60
  text "X" at 12256.46,4946.92 h60
  text "ANSI IPC-6012 TYPE 3 CLASS 2" at 12434.48,4946.92 h60
  text "OTHER +/-" at 12434.46,4802.73 h60
  text "BOW & TWIST:" at 11408.23,4657.54 h60
  text "X" at 12256.46,4657.54 h60
  text "ANSI IPC-6012 TYPE 3 CLASS 2" at 12434.48,4657.54 h60
  text "OTHER +/-" at 12434.46,4510.85 h60
  text "DRILLING:" at 11333.46,4380.23 h60
  text "NC_DRILL FILES" at 13094.46,4275.04 h60
  text "REFERENCE:" at 11408.23,4271.1 h60
  text "X" at 12065.46,4271.01 h60
  text "AS SHOWN" at 12243.46,4271.1 h60
  text "X" at 12966.46,4271.1 h60
  text "OTHER" at 13392.46,4128.85 h60
  text "PTH COPPER THICKNESS:" at 11407.91,4125.32 h60
  text "X" at 12547.14,4125.32 h60
  text "20-30 um" at 12675.14,4125.32 h60
  text "BOARD FINISH:" at 11333.46,3977.73 h60
  text "SILKSCREEN:" at 11488.68,3867.6 h60
  text "X" at 12446.46,3867.6 h60
  text "TOP" at 12563.46,3867.6 h60
  text "X" at 12956.46,3867.6 h60
  text "BOTTOM" at 13074.46,3867.6 h60
  text "SILKSCREEN COLOR:" at 11488.68,3712.41 h60
  text "X" at 12445.46,3712.41 h60
  text "WHITE" at 12563.46,3712.41 h60
  text "OTHER" at 13074.46,3712.41 h60
  text "X" at 12576.46,3568.96 h60
  text "GREEN" at 12694.46,3568.96 h60
  text "OTHER" at 13312.46,3568.96 h60
  text "SOLDER RESIST COLOR:" at 11488.68,3562.1 h60
  text "X" at 12576.46,3414.71 h60
  text "MATTE" at 12694.46,3414.71 h60
  text "SEMI-GLOSS" at 13312,3414.07 h60
  text "IMMERSION GOLD (ENIG)" at 12394.46,3241.94 h60
  text "ENEPIG" at 13732,3234.72 h60
  text "SURFACE FINISH:" at 11333.46,3233.72 h60
  text "X" at 12216.46,3233.72 h60
  text "IMM. TIN/SILVER OR EQUIV" at 11663,3096.4 h60
  text "OTHER" at 13094.46,3092.47 h60
  text "ARRAY/PANEL:" at 11333.46,2937.09 h60
  text "CUT AND TRIM PER M1 BOARD OUTLINE" at 12394.46,2928.87 h60
  text "X" at 13090.55,2795.28 h60
  text "N.C. ROUTE" at 12394.46,2792.9 h60
  text "V. SCORE" at 13260.46,2792.9 h60
  text "CERTIFICATION:" at 11333.46,2663.77 h60
  text "MATERIALS AND WORKMANSHIP FOR ALL PCBS" at 12058.46,2663.77 h60
  text "TO MEET OR EXCEED THE REQUIREMENTS OF:" at 12058.46,2569.71 h60
  text "X" at 11695.97,2441.08 h60
  text "ANSI IPC-A-600F CLASS ->" at 11823.96,2441.08 h60
  text "X" at 13471.97,2441.08 h60
  text "2" at 13581.96,2441.08 h60
  text "1" at 13266.96,2439.58 h60
  text "3" at 13935.96,2439.58 h60
  text "X" at 12507.97,2293.39 h60
  text "RoHS" at 12635.96,2293.39 h60
  text "OTHER" at 13280.36,2293.39 h60
  text "PER ORDER" at 13677.42,2293.39 h60
  text "ALL BOARDS MUST MEET OR EXCEED UL94V-0 REQUIREMENTS." at 11361,2139.57 h60
  text "PCB MUST BEAR THE UL94V-0 UL REGISTERED MATERIAL ID NUMBER" at 11361,2023.5 h60
  text "ADDITIONAL REQUIREMENTS:" at 11333.46,1854.08 h60
  text "MICROSECTION:" at 11408.23,1746.95 h60
  text "YES" at 12313.96,1746.95 h60
  text "REQUIRED" at 13175.46,1602.62 h60
  text "BARE BOARD ELEC. TEST:" at 11408.23,1599.76 h60
  text "NONE" at 12713.96,1599.76 h60
  text "X" at 13057.46,1599.76 h60
  text "PER ORDER" at 13767.46,1599.76 h60
  text "X" at 13451.17,1580.08 h60
  text "X" at 11466.54,1456.69 h60
  text "7.87 MIL VIAS REQUIRE NON-CONDUCTIVE FILL AND PLANARIZE" at 11576.38,1394.82 h59
  text "XX MIL VIAS REQUIRE CONDUCTIVE FILL AND PLANARIZE" at 11584.38,1290.84 h60
  text "X" at 12821.24,1196.22 h60
  text "OUTER XX MIL TRACES REQUIRE 50 OHM SINGLE-ENDED IMPEDANCE" at 11583.39,1127.46 h58
  text "LAYER 2 & 3 (INNER LAYERS) XX MIL WIDE, XX MIL SPACE / TRACES REQUIRE 100 OHM DIFFERENTIAL IMPEDANCE" at 11575.39,891.74 h60
  text ".Layer_Name" at 577,-858.49 h60
M11 Gerber Information:
  lines w10: -292,-930.17 6308,-930.17 ; -292,-726.83 6310,-726.83 ; -292,-523.5 -292,-1133.5 3713,-1133.5 6310,-1133.5 6310,-523.5 -291.5,-523.5 -291.5,-1133.5 1284,-1133.5 ; 2173,-1133.5 2173,-523.5 ; 3440,-726.83 3440,-523.5 ; 4280,-726.83 4280,-523.5 ; 4902,-1140 4902,-937.17
  text "ALL ARTWORK VIEWED FROM TOP SIDE" at -228.5,-655.67 h60
  text "BOARD #:" at 2248,-655.67 h60
  text ".PRJ_Number" at 2793.5,-655.67 h60
  text "REV:" at 3638,-655.67 h60
  text ".PCB_Rev" at 3929.5,-655.67 h60
  text "SVN REV:" at 4476,-655.67 h60
  text ".VersionControl_RevNumber" at 4982,-655.67 h60
  text "LAYER NAME =" at -228.5,-858.49 h60
  text "TID #:" at 2248,-859 h60
  text ".TID" at 2793.5,-859 h60
  text "PLOT NAME =" at -228.5,-1064.34 h60
  text ".plot_File_Name" at 577,-1064.34 h60
  text "GENERATED    :" at 2250,-1064.34 h60
  text ".Print_Date" at 3119.5,-1064.34 h60
  text ".Print_Time" at 3848.5,-1064.34 h60
  text "TEXAS INSTRUMENTS" at 5113,-1064.34 h60
M12 Stackup:
  drawing of 399 lines, arcs and shapes, not listed
  text "Layer" at 4738.83,6633.94 h60
  text "Name" at 5148.74,6633.94 h60
  text "Material" at 6088.48,6633.94 h60
  text "Thickness" at 6948.25,6633.94 h60
  text "Constant" at 7598.08,6633.94 h60
  text "Board Layer Stack" at 8167.94,6633.94 h60
  text "Top Overlay" at 5148.74,6513.94 h60
  text "Top Solder" at 5148.74,6393.94 h60
  text "Solder Resist" at 6088.48,6393.94 h60
  text "0.40mil" at 6948.25,6393.94 h60
  text "3.5" at 7598.08,6393.94 h60
  text "1" at 4738.83,6273.94 h60
  text "Top Layer" at 5148.74,6273.94 h60
  text "2.76mil" at 6948.25,6273.94 h60
  text "Dielectric 1" at 5148.74,6153.94 h60
  text "PP-006" at 6088.48,6153.94 h60
  text "8.00mil" at 6948.25,6153.94 h60
  text "4.1" at 7598.08,6153.94 h60
  text "2" at 4738.83,6033.94 h60
  text "Signal Layer 1" at 5148.74,6033.94 h60
  text "CF-004" at 6088.48,6033.94 h60
  text "2.76mil" at 6948.25,6033.94 h60
  text "Dielectric 2" at 5148.74,5913.94 h60
  text "PP-006" at 6088.48,5913.94 h60
  text "8.00mil" at 6948.25,5913.94 h60
  text "4.1" at 7598.08,5913.94 h60
  text "3" at 4738.83,5793.94 h60
  text "Signal Layer 2" at 5148.74,5793.94 h60
  text "CF-004" at 6088.48,5793.94 h60
  text "2.76mil" at 6948.25,5793.94 h60
  text "Dielectric3" at 5148.74,5673.94 h60
  text "FR-4 High Tg" at 6088.48,5673.94 h60
  text "12.00mil" at 6948.25,5673.94 h60
  text "4.8" at 7598.08,5673.94 h60
  text "4" at 4738.83,5553.94 h60
  text "Signal Layer 3" at 5148.74,5553.94 h60
  text "CF-004" at 6088.48,5553.94 h60
  text "2.76mil" at 6948.25,5553.94 h60
  text "Dielectric 4" at 5148.74,5433.94 h60
  text "PP-006" at 6088.48,5433.94 h60
  text "8.00mil" at 6948.25,5433.94 h60
  text "4.1" at 7598.08,5433.94 h60
  text "5" at 4738.83,5313.94 h60
  text "Signal Layer 4" at 5148.74,5313.94 h60
  text "CF-004" at 6088.48,5313.94 h60
  text "2.76mil" at 6948.25,5313.94 h60
  text "Dielectric 5" at 5148.74,5193.94 h60
  text "PP-006" at 6088.48,5193.94 h60
  text "8.00mil" at 6948.25,5193.94 h60
  text "4.1" at 7598.08,5193.94 h60
  text "6" at 4738.83,5073.94 h60
  text "Bottom Layer" at 5148.74,5073.94 h60
  text "2.76mil" at 6948.25,5073.94 h60
  text "Bottom Solder" at 5148.74,4953.94 h60
  text "Solder Resist" at 6088.48,4953.94 h60
  text "0.40mil" at 6948.25,4953.94 h60
  text "3.5" at 7598.08,4953.94 h60
  text "Bottom Overlay" at 5148.74,4833.94 h60
  text "Total board thickness:" at 4738.83,4713.94 h60
  text "61.34mil" at 6948.25,4713.94 h60
  text ".Layer_Name" at 577,-858.49 h60
M13 Component Bodies Top:
  text ".Layer_Name" at 577,-858.49 h60
M14 Component Bodies Bottom:
  text ".Layer_Name" at 577,-858.49 h60
M15 Courtyards Top:
  text ".Layer_Name" at 577,-858.49 h60
M16 Courtyards Bottom:
  text ".Layer_Name" at 577,-858.49 h60
Drill Drawing:
  circle w10: c6577.59,2867.39 r27.63
  lines w10: 6549.96,2715.44 6605.22,2715.44 6605.22,2770.7 6549.96,2770.7 6549.96,2715.44 ; 6549.96,2964.08 6605.22,2964.08 6605.22,3019.34 6549.96,3019.34 6549.96,2964.08 ; 6549.96,3143.66 6605.22,3143.66 6577.59,3088.4 6549.96,3143.66 ; 6549.96,3226.54 6563.78,3226.54 6563.78,3212.72 6591.4,3212.72 6591.4,3226.54 6605.22,3226.54 6605.22,3254.16 6591.4,3254.16 6591.4,3267.98 6563.78,3267.98 6563.78,3254.16 6549.96,3254.16 6549.96,3226.54 ; 6549.96,3350.86 6563.78,3350.86 6577.59,3337.04 6591.4,3350.86 6605.22,3350.86 6591.4,3364.67 6605.22,3378.48 6591.4,3378.48 6577.59,3392.3 6563.78,3378.48 6549.96,3378.48 6563.78,3364.67 6549.96,3350.86 ; 6549.96,3461.36 6549.96,3475.18 6563.78,3488.99 6549.96,3502.8 6549.96,3516.62 6563.78,3516.62 6577.59,3502.8 6591.4,3516.62 6605.22,3516.62 6605.22,3502.8 6591.4,3488.99 6605.22,3475.18 6605.22,3461.36 6591.4,3461.36 6577.59,3475.18 6563.78,3461.36 6549.96,3461.36 ; 6561.01,2975.14 6594.17,2975.14 6594.17,3008.29 6561.01,3008.29 6561.01,2975.14
  lines w12: 6499.87,2678.15 9731.36,2678.15 ; 6499.87,3548.39 9731.36,3548.39 ; 6837.73,2553.83 6837.73,3672.71 ; 7169.73,2553.83 7169.73,3672.71 ; 7806.3,2553.83 7806.3,3672.71 ; 8065.44,2553.83 8065.44,3672.71 ; 8440.6,2553.83 8440.6,3672.71 ; 9164.93,2553.83 9164.93,3672.71 ; 6499.87,2553.83 9731.36,2553.83 9731.36,3672.71 6499.87,3672.71 6499.87,2553.83
  text "Symbol" at 6574.46,3585.68 h72
  text "Quantity" at 6875.03,3585.68 h72
  text "Finished Hole Size" at 7207.03,3585.68 h72
  text "Plated" at 7843.59,3585.68 h72
  text "Hole Type" at 8102.73,3585.68 h72
  text "Drill Layer Pair" at 8477.89,3585.68 h72
  text "Hole Tolerance" at 9202.22,3585.68 h72
  text "2" at 6875.03,3461.36 h60
  text "204.72mil (5.200mm)" at 7207.03,3461.36 h60
  text "NPTH" at 7843.59,3461.36 h60
  text "Round" at 8102.73,3461.36 h60
  text "Top Layer - Bottom Layer" at 8477.89,3461.36 h60
  text "18" at 6875.03,3337.04 h60
  text "7.87mil (0.200mm)" at 7207.03,3337.04 h60
  text "PTH" at 7843.59,3337.04 h60
  text "Round" at 8102.73,3337.04 h60
  text "Top Layer - Bottom Layer" at 8477.89,3337.04 h60
  text "277" at 6875.03,3212.72 h60
  text "10.00mil (0.254mm)" at 7207.03,3212.72 h60
  text "PTH" at 7843.59,3212.72 h60
  text "Round" at 8102.73,3212.72 h60
  text "Top Layer - Bottom Layer" at 8477.89,3212.72 h60
  text "12" at 6875.03,3088.4 h60
  text "40.00mil (1.016mm)" at 7207.03,3088.4 h60
  text "PTH" at 7843.59,3088.4 h60
  text "Round" at 8102.73,3088.4 h60
  text "Top Layer - Bottom Layer" at 8477.89,3088.4 h60
  text "2" at 6875.03,2964.08 h60
  text "55.12mil (1.400mm)" at 7207.03,2964.08 h60
  text "PTH" at 7843.59,2964.08 h60
  text "Round" at 8102.73,2964.08 h60
  text "Top Layer - Bottom Layer" at 8477.89,2964.08 h60
  text "16" at 6875.03,2839.76 h60
  text "72.84mil (1.850mm)" at 7207.03,2839.76 h60
  text "PTH" at 7843.59,2839.76 h60
  text "Round" at 8102.73,2839.76 h60
  text "Top Layer - Bottom Layer" at 8477.89,2839.76 h60
  text "4" at 6875.03,2715.44 h60
  text "125.98mil (3.200mm)" at 7207.03,2715.44 h60
  text "PTH" at 7843.59,2715.44 h60
  text "Round" at 8102.73,2715.44 h60
  text "Top Layer - Bottom Layer" at 8477.89,2715.44 h60
  text "331 Total" at 6875.03,2591.12 h60
  text ".Layer_Name" at 577,-858.49 h60
M17 Embedded Cavity:
  text ".Layer_Name" at 577,-858.49 h60
M18 Embedded Assembly:
  text ".Layer_Name" at 577,-858.49 h60
M19 Embedded Keepout:
  text ".Layer_Name" at 577,-858.49 h60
